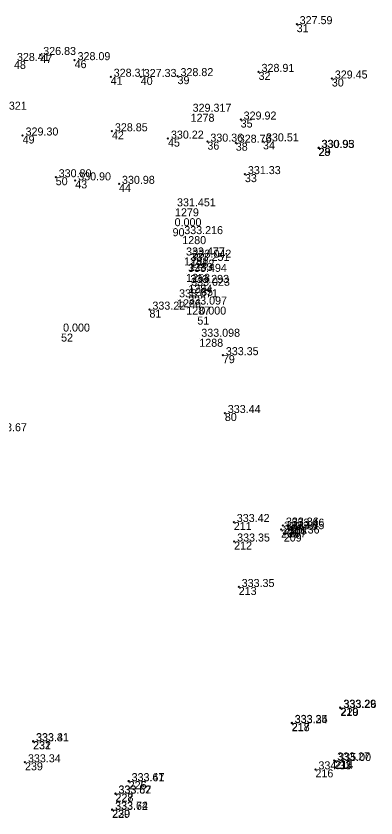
# Model space of a CAD drawing. Extents: x -829398 to -819400, y -1074439 to -1067977.
# Drawn here: x -825708.1 to -825654.2, y -1070203.9 to -1070083.6 of the extents above; entities that cross this region are included whole.
import ezdxf

# ---------------------------------------------------------------- set-up
doc = ezdxf.new("R2010")
doc.units = 0
doc.layers.add('Vrstva 60', color=7, linetype='Continuous')
doc.layers.add('Vrstva 61', color=7, linetype='Continuous')

msp = doc.modelspace()

# ---------------------------------------------------------------- linework, layer by layer
at = {"layer": 'Vrstva 60'}
for p, q in [((-825666.056, -1070084.864), (-825666.156, -1070084.764)), ((-825666.056, -1070084.864), (-825666.156, -1070084.964)), ((-825666.056, -1070084.864), (-825665.956, -1070084.764)), ((-825666.056, -1070084.864), (-825665.956, -1070084.964)), ((-825704.452, -1070089.481), (-825704.552, -1070089.381)), ((-825704.452, -1070089.481), (-825704.552, -1070089.581)), ((-825704.452, -1070089.481), (-825704.352, -1070089.381)), ((-825704.452, -1070089.481), (-825704.352, -1070089.581)), ((-825699.31, -1070090.258), (-825699.41, -1070090.158)), ((-825699.31, -1070090.258), (-825699.41, -1070090.358)), ((-825699.31, -1070090.258), (-825699.21, -1070090.158)), ((-825699.31, -1070090.258), (-825699.21, -1070090.358)), ((-825693.902, -1070092.744), (-825694.002, -1070092.644)), ((-825693.902, -1070092.744), (-825694.002, -1070092.844)), ((-825693.902, -1070092.744), (-825693.802, -1070092.644)), ((-825693.902, -1070092.744), (-825693.802, -1070092.844)), ((-825689.405, -1070092.776), (-825689.505, -1070092.676)), ((-825689.405, -1070092.776), (-825689.505, -1070092.876)), ((-825689.405, -1070092.776), (-825689.305, -1070092.676)), ((-825689.405, -1070092.776), (-825689.305, -1070092.876)), ((-825683.9, -1070092.653), (-825684, -1070092.553)), ((-825683.9, -1070092.653), (-825684, -1070092.753)), ((-825683.9, -1070092.653), (-825683.8, -1070092.553)), ((-825683.9, -1070092.653), (-825683.8, -1070092.753)), ((-825671.761, -1070092.019), (-825671.861, -1070091.919)), ((-825671.761, -1070092.019), (-825671.861, -1070092.119)), ((-825671.761, -1070092.019), (-825671.661, -1070091.919)), ((-825671.761, -1070092.019), (-825671.661, -1070092.119)), ((-825660.796, -1070093.009), (-825660.896, -1070092.909)), ((-825660.796, -1070093.009), (-825660.896, -1070093.109)), ((-825660.796, -1070093.009), (-825660.696, -1070092.909)), ((-825660.796, -1070093.009), (-825660.696, -1070093.109)), ((-825681.936, -1070098.294), (-825681.936, -1070098.294)), ((-825674.443, -1070099.163), (-825674.543, -1070099.063)), ((-825674.443, -1070099.163), (-825674.543, -1070099.263)), ((-825674.443, -1070099.163), (-825674.343, -1070099.063)), ((-825674.443, -1070099.163), (-825674.343, -1070099.263)), ((-825693.72, -1070100.922), (-825693.82, -1070100.822)), ((-825693.72, -1070100.922), (-825693.82, -1070101.022)), ((-825693.72, -1070100.922), (-825693.62, -1070100.822)), ((-825693.72, -1070100.922), (-825693.62, -1070101.022)), ((-825707.093, -1070101.555), (-825707.193, -1070101.455)), ((-825707.093, -1070101.555), (-825707.193, -1070101.655)), ((-825707.093, -1070101.555), (-825706.993, -1070101.455)), ((-825707.093, -1070101.555), (-825706.993, -1070101.655)), ((-825685.329, -1070102.02), (-825685.429, -1070101.92)), ((-825685.329, -1070102.02), (-825685.429, -1070102.12)), ((-825685.329, -1070102.02), (-825685.229, -1070101.92)), ((-825685.329, -1070102.02), (-825685.229, -1070102.12)), ((-825679.428, -1070102.474), (-825679.528, -1070102.374)), ((-825679.428, -1070102.474), (-825679.328, -1070102.374)), ((-825671.102, -1070102.432), (-825671.202, -1070102.332)), ((-825671.102, -1070102.432), (-825671.202, -1070102.532)), ((-825671.102, -1070102.432), (-825671.002, -1070102.332)), ((-825671.102, -1070102.432), (-825671.002, -1070102.532)), ((-825679.428, -1070102.474), (-825679.528, -1070102.574)), ((-825679.428, -1070102.474), (-825679.328, -1070102.574)), ((-825675.179, -1070102.633), (-825675.279, -1070102.533)), ((-825675.179, -1070102.633), (-825675.279, -1070102.733)), ((-825675.179, -1070102.633), (-825675.079, -1070102.533)), ((-825675.179, -1070102.633), (-825675.079, -1070102.733)), ((-825662.812, -1070103.412), (-825662.912, -1070103.312)), ((-825662.812, -1070103.412), (-825662.912, -1070103.512)), ((-825662.746, -1070103.417), (-825662.846, -1070103.317)), ((-825662.746, -1070103.417), (-825662.846, -1070103.517)), ((-825662.812, -1070103.412), (-825662.712, -1070103.312)), ((-825662.812, -1070103.412), (-825662.712, -1070103.512)), ((-825662.746, -1070103.417), (-825662.646, -1070103.317)), ((-825662.746, -1070103.417), (-825662.646, -1070103.517)), ((-825673.806, -1070107.342), (-825673.906, -1070107.242)), ((-825673.806, -1070107.342), (-825673.706, -1070107.242)), ((-825702.136, -1070107.812), (-825702.236, -1070107.712)), ((-825702.136, -1070107.812), (-825702.236, -1070107.912)), ((-825702.136, -1070107.812), (-825702.036, -1070107.712)), ((-825702.136, -1070107.812), (-825702.036, -1070107.912)), ((-825699.215, -1070108.279), (-825699.315, -1070108.179)), ((-825699.215, -1070108.279), (-825699.315, -1070108.379)), ((-825699.215, -1070108.279), (-825699.115, -1070108.179)), ((-825699.215, -1070108.279), (-825699.115, -1070108.379)), ((-825673.806, -1070107.342), (-825673.906, -1070107.442)), ((-825673.806, -1070107.342), (-825673.706, -1070107.442)), ((-825692.66, -1070108.8), (-825692.76, -1070108.7)), ((-825692.66, -1070108.8), (-825692.76, -1070108.9)), ((-825692.66, -1070108.8), (-825692.56, -1070108.7)), ((-825692.66, -1070108.8), (-825692.56, -1070108.9)), ((-825684.274, -1070112.473), (-825684.274, -1070112.473)), ((-825684.636, -1070115.452), (-825684.636, -1070115.452)), ((-825683.188, -1070116.638), (-825683.188, -1070116.638)), ((-825682.923, -1070119.841), (-825682.923, -1070119.841)), ((-825681.951, -1070120.172), (-825681.951, -1070120.172)), ((-825682.222, -1070120.651), (-825682.222, -1070120.651)), ((-825682.614, -1070122.295), (-825682.614, -1070122.295)), ((-825682.279, -1070123.951), (-825682.279, -1070123.951)), ((-825682.16, -1070124.378), (-825682.16, -1070124.378)), ((-825683.963, -1070126.111), (-825683.963, -1070126.111)), ((-825688.104, -1070127.656), (-825688.204, -1070127.556)), ((-825688.104, -1070127.656), (-825688.204, -1070127.756)), ((-825688.104, -1070127.656), (-825688.004, -1070127.556)), ((-825688.104, -1070127.656), (-825688.004, -1070127.756)), ((-825682.592, -1070127.2), (-825682.592, -1070127.2)), ((-825680.928, -1070128.701), (-825680.928, -1070128.701)), ((-825701.333, -1070131.247), (-825701.333, -1070131.247)), ((-825680.639, -1070132.026), (-825680.639, -1070132.026)), ((-825677.112, -1070134.484), (-825677.212, -1070134.384)), ((-825677.112, -1070134.484), (-825677.212, -1070134.584)), ((-825677.112, -1070134.484), (-825677.012, -1070134.384)), ((-825677.112, -1070134.484), (-825677.012, -1070134.584)), ((-825676.815, -1070143.157), (-825676.915, -1070143.057)), ((-825676.815, -1070143.157), (-825676.915, -1070143.257)), ((-825676.815, -1070143.157), (-825676.715, -1070143.057)), ((-825676.815, -1070143.157), (-825676.715, -1070143.257)), ((-825675.472, -1070159.495), (-825675.572, -1070159.395)), ((-825675.472, -1070159.495), (-825675.572, -1070159.595)), ((-825675.472, -1070159.495), (-825675.372, -1070159.395)), ((-825675.472, -1070159.495), (-825675.372, -1070159.595)), ((-825668.115, -1070160.028), (-825668.215, -1070159.928)), ((-825668.115, -1070160.028), (-825668.215, -1070160.128)), ((-825668.115, -1070160.028), (-825668.015, -1070159.928)), ((-825668.115, -1070160.028), (-825668.015, -1070160.128)), ((-825667.269, -1070160.184), (-825667.369, -1070160.084)), ((-825667.269, -1070160.184), (-825667.169, -1070160.084)), ((-825668.399, -1070160.626), (-825668.499, -1070160.526)), ((-825668.399, -1070160.626), (-825668.499, -1070160.726)), ((-825668.399, -1070160.626), (-825668.299, -1070160.526)), ((-825668.399, -1070160.626), (-825668.299, -1070160.726)), ((-825667.991, -1070161.226), (-825668.091, -1070161.126)), ((-825667.991, -1070161.226), (-825668.091, -1070161.326)), ((-825667.991, -1070161.226), (-825667.891, -1070161.126)), ((-825667.991, -1070161.226), (-825667.891, -1070161.326)), ((-825667.274, -1070160.57), (-825667.374, -1070160.47)), ((-825667.274, -1070160.57), (-825667.374, -1070160.67)), ((-825667.269, -1070160.184), (-825667.369, -1070160.284)), ((-825667.274, -1070160.57), (-825667.174, -1070160.47)), ((-825667.274, -1070160.57), (-825667.174, -1070160.67)), ((-825667.269, -1070160.184), (-825667.169, -1070160.284)), ((-825675.42, -1070162.416), (-825675.52, -1070162.316)), ((-825675.42, -1070162.416), (-825675.52, -1070162.516)), ((-825675.42, -1070162.416), (-825675.32, -1070162.316)), ((-825675.42, -1070162.416), (-825675.32, -1070162.516)), ((-825674.738, -1070169.233), (-825674.838, -1070169.133)), ((-825674.738, -1070169.233), (-825674.838, -1070169.333)), ((-825674.738, -1070169.233), (-825674.638, -1070169.133)), ((-825674.738, -1070169.233), (-825674.638, -1070169.333)), ((-825659.526, -1070187.324), (-825659.626, -1070187.224)), ((-825659.526, -1070187.324), (-825659.626, -1070187.424)), ((-825659.473, -1070187.382), (-825659.573, -1070187.282)), ((-825659.473, -1070187.382), (-825659.573, -1070187.482)), ((-825659.526, -1070187.324), (-825659.426, -1070187.224)), ((-825659.526, -1070187.324), (-825659.426, -1070187.424)), ((-825659.473, -1070187.382), (-825659.373, -1070187.282)), ((-825659.473, -1070187.382), (-825659.373, -1070187.482)), ((-825666.802, -1070189.61), (-825666.902, -1070189.51)), ((-825666.802, -1070189.61), (-825666.902, -1070189.71)), ((-825666.792, -1070189.653), (-825666.892, -1070189.553)), ((-825666.792, -1070189.653), (-825666.892, -1070189.753)), ((-825666.802, -1070189.61), (-825666.702, -1070189.51)), ((-825666.802, -1070189.61), (-825666.702, -1070189.71)), ((-825666.792, -1070189.653), (-825666.692, -1070189.553)), ((-825666.792, -1070189.653), (-825666.692, -1070189.753)), ((-825705.535, -1070192.344), (-825705.635, -1070192.244)), ((-825705.535, -1070192.344), (-825705.635, -1070192.444)), ((-825705.523, -1070192.38), (-825705.623, -1070192.28)), ((-825705.523, -1070192.38), (-825705.623, -1070192.48)), ((-825705.535, -1070192.344), (-825705.435, -1070192.244)), ((-825705.535, -1070192.344), (-825705.435, -1070192.444)), ((-825705.523, -1070192.38), (-825705.423, -1070192.28)), ((-825705.523, -1070192.38), (-825705.423, -1070192.48)), ((-825706.74, -1070195.514), (-825706.84, -1070195.414)), ((-825706.74, -1070195.514), (-825706.84, -1070195.614)), ((-825706.74, -1070195.514), (-825706.64, -1070195.414)), ((-825706.74, -1070195.514), (-825706.64, -1070195.614)), ((-825660.433, -1070195.24), (-825660.533, -1070195.14)), ((-825660.433, -1070195.24), (-825660.533, -1070195.34)), ((-825660.433, -1070195.24), (-825660.333, -1070195.14)), ((-825660.433, -1070195.24), (-825660.333, -1070195.34)), ((-825660.279, -1070195.32), (-825660.379, -1070195.22)), ((-825660.279, -1070195.32), (-825660.379, -1070195.42)), ((-825660.279, -1070195.32), (-825660.179, -1070195.22)), ((-825660.279, -1070195.32), (-825660.179, -1070195.42)), ((-825663.247, -1070196.572), (-825663.347, -1070196.472)), ((-825663.247, -1070196.572), (-825663.347, -1070196.672)), ((-825663.247, -1070196.572), (-825663.147, -1070196.472)), ((-825663.247, -1070196.572), (-825663.147, -1070196.672)), ((-825691.221, -1070198.357), (-825691.321, -1070198.257)), ((-825691.221, -1070198.357), (-825691.321, -1070198.457)), ((-825691.212, -1070198.339), (-825691.312, -1070198.239)), ((-825691.212, -1070198.339), (-825691.312, -1070198.439)), ((-825691.221, -1070198.357), (-825691.121, -1070198.257)), ((-825691.221, -1070198.357), (-825691.121, -1070198.457)), ((-825691.212, -1070198.339), (-825691.112, -1070198.239)), ((-825691.212, -1070198.339), (-825691.112, -1070198.439)), ((-825693.192, -1070200.187), (-825693.292, -1070200.087)), ((-825693.192, -1070200.187), (-825693.292, -1070200.287)), ((-825693.183, -1070200.225), (-825693.283, -1070200.125)), ((-825693.183, -1070200.225), (-825693.283, -1070200.325)), ((-825693.192, -1070200.187), (-825693.092, -1070200.087)), ((-825693.192, -1070200.187), (-825693.092, -1070200.287)), ((-825693.183, -1070200.225), (-825693.083, -1070200.125)), ((-825693.183, -1070200.225), (-825693.083, -1070200.325)), ((-825693.691, -1070202.641), (-825693.791, -1070202.541)), ((-825693.691, -1070202.641), (-825693.791, -1070202.741)), ((-825693.684, -1070202.601), (-825693.784, -1070202.501)), ((-825693.684, -1070202.601), (-825693.784, -1070202.701)), ((-825693.691, -1070202.641), (-825693.591, -1070202.541)), ((-825693.691, -1070202.641), (-825693.591, -1070202.741)), ((-825693.684, -1070202.601), (-825693.584, -1070202.501)), ((-825693.684, -1070202.601), (-825693.584, -1070202.701))]:
    msp.add_line(p, q, dxfattribs=at)

# ---------------------------------------------------------------- texts
for s, p in [('31', (-825666.056, -1070086.064)), ('48', (-825708.389, -1070091.58)), ('47', (-825704.452, -1070090.681)), ('46', (-825699.31, -1070091.458)), ('41', (-825693.902, -1070093.944)), ('40', (-825689.405, -1070093.976)), ('39', (-825683.9, -1070093.853)), ('32', (-825671.761, -1070093.219)), ('30', (-825660.796, -1070094.209)), ('1278', (-825681.936, -1070099.494)), ('35', (-825674.443, -1070100.363)), ('42', (-825693.72, -1070102.122)), ('49', (-825707.093, -1070102.755)), ('45', (-825685.329, -1070103.22)), ('34', (-825671.102, -1070103.632)), ('36', (-825679.428, -1070103.674)), ('38', (-825675.179, -1070103.833)), ('28', (-825662.812, -1070104.612)), ('29', (-825662.746, -1070104.617)), ('50', (-825702.136, -1070109.012)), ('43', (-825699.215, -1070109.479)), ('33', (-825673.806, -1070108.542)), ('44', (-825692.66, -1070110)), ('1279', (-825684.274, -1070113.673)), ('90', (-825684.636, -1070116.652)), ('1280', (-825683.188, -1070117.838)), ('1281', (-825682.923, -1070121.041)), ('1282', (-825681.951, -1070121.372)), ('1283', (-825682.222, -1070121.851)), ('1258', (-825682.614, -1070123.495)), ('1284', (-825682.279, -1070125.151)), ('1285', (-825682.16, -1070125.578)), ('1286', (-825683.963, -1070127.311)), ('81', (-825688.104, -1070128.856)), ('1287', (-825682.592, -1070128.4)), ('51', (-825680.928, -1070129.901)), ('52', (-825701.333, -1070132.447)), ('1288', (-825680.639, -1070133.226)), ('79', (-825677.112, -1070135.684)), ('80', (-825676.815, -1070144.357)), ('211', (-825675.472, -1070160.695)), ('210', (-825668.115, -1070161.228)), ('208', (-825668.399, -1070161.826)), ('209', (-825667.991, -1070162.426)), ('207', (-825667.274, -1070161.77)), ('206', (-825667.269, -1070161.384)), ('212', (-825675.42, -1070163.616)), ('213', (-825674.738, -1070170.433)), ('219', (-825659.526, -1070188.524)), ('220', (-825659.473, -1070188.582)), ('217', (-825666.802, -1070190.81)), ('218', (-825666.792, -1070190.853)), ('232', (-825705.535, -1070193.544)), ('231', (-825705.523, -1070193.58)), ('239', (-825706.74, -1070196.714)), ('215', (-825660.433, -1070196.44)), ('214', (-825660.279, -1070196.52)), ('216', (-825663.247, -1070197.772)), ('226', (-825691.221, -1070199.557)), ('225', (-825691.212, -1070199.539)), ('227', (-825693.192, -1070201.387)), ('228', (-825693.183, -1070201.425)), ('229', (-825693.691, -1070203.841)), ('230', (-825693.684, -1070203.801))]:
    msp.add_text(s, height=1.2, dxfattribs=at).set_placement(p)
at = {"layer": 'Vrstva 61'}
for s, p in [(' 327.59', (-825666.056, -1070084.864)), (' 328.41', (-825708.389, -1070090.38)), (' 326.83', (-825704.452, -1070089.481)), (' 328.09', (-825699.31, -1070090.258)), (' 328.31', (-825693.902, -1070092.744)), (' 327.33', (-825689.405, -1070092.776)), (' 328.82', (-825683.9, -1070092.653)), (' 328.91', (-825671.761, -1070092.019)), (' 329.45', (-825660.796, -1070093.009)), ('329.321', (-825712.272, -1070097.687)), ('329.317', (-825681.636, -1070097.994)), (' 329.92', (-825674.443, -1070099.163)), (' 328.85', (-825693.72, -1070100.922)), (' 329.30', (-825707.093, -1070101.555)), (' 330.22', (-825685.329, -1070102.02)), (' 330.51', (-825671.102, -1070102.432)), (' 330.36', (-825679.428, -1070102.474)), (' 328.76', (-825675.179, -1070102.633)), (' 330.95', (-825662.812, -1070103.412)), (' 330.93', (-825662.746, -1070103.417)), (' 330.80', (-825702.136, -1070107.812)), (' 330.90', (-825699.215, -1070108.279)), (' 331.33', (-825673.806, -1070107.342)), (' 330.98', (-825692.66, -1070108.8)), ('331.451', (-825683.974, -1070112.173)), ('0.000', (-825684.336, -1070115.152)), ('333.216', (-825682.888, -1070116.338)), ('333.477', (-825682.623, -1070119.541)), ('333.251', (-825681.922, -1070120.351)), ('333.042', (-825681.651, -1070119.872)), ('333.494', (-825682.314, -1070121.995)), ('333.293', (-825681.979, -1070123.651)), ('333.023', (-825681.86, -1070124.078)), ('333.071', (-825683.663, -1070125.811)), (' 333.22', (-825688.104, -1070127.656)), ('333.097', (-825682.292, -1070126.9)), ('0.000', (-825680.628, -1070128.401)), ('0.000', (-825701.033, -1070130.947)), ('333.098', (-825680.339, -1070131.726)), (' 333.35', (-825677.112, -1070134.484)), (' 333.44', (-825676.815, -1070143.157)), (' 333.67', (-825711.806, -1070145.889)), (' 333.42', (-825675.472, -1070159.495)), (' 333.36', (-825668.115, -1070160.028)), (' 333.45', (-825668.399, -1070160.626)), (' 333.36', (-825667.991, -1070161.226)), (' 333.45', (-825667.274, -1070160.57)), (' 333.46', (-825667.269, -1070160.184)), (' 333.35', (-825675.42, -1070162.416)), (' 333.35', (-825674.738, -1070169.233)), (' 333.29', (-825659.526, -1070187.324)), (' 333.26', (-825659.473, -1070187.382)), (' 333.35', (-825666.802, -1070189.61)), (' 333.24', (-825666.792, -1070189.653)), (' 333.41', (-825705.535, -1070192.344)), (' 333.31', (-825705.523, -1070192.38)), (' 333.34', (-825706.74, -1070195.514)), (' 333.27', (-825660.433, -1070195.24)), (' 335.00', (-825660.279, -1070195.32)), (' 334.33', (-825663.247, -1070196.572)), (' 333.61', (-825691.221, -1070198.357)), (' 333.47', (-825691.212, -1070198.339)), (' 333.52', (-825693.192, -1070200.187)), (' 333.67', (-825693.183, -1070200.225)), (' 333.62', (-825693.691, -1070202.641)), (' 333.74', (-825693.684, -1070202.601))]:
    msp.add_text(s, height=1.2, dxfattribs=at).set_placement(p)

doc.saveas('drawing.dxf')
